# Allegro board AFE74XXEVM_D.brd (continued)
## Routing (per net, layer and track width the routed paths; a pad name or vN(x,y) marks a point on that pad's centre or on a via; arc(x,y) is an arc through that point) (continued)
FMC_SCL: length 50.4
  TOP w0.127: U31.6 189.03,22.71 190.07,23.75 190.07,27.48 J37.2 190.04,27.58 188.14,29.49 188.14,37.85 198.73,48.44 213.03,48.44 213.55,48.96 213.55,50.61 v2(212.73,51.43)
FMC_SDA: length 45.5
  TOP w0.127: U31.5 187.25,23.98 186.74,24.49 186.74,26.75 J37.1 187.5,38.05 199.03,49.58 212.14,49.58 v2(212.73,50.16)
FMC_SPIACLK: length 94.6
  L4_SIG w0.127: v2(211.46,75.56) 211.33,75.56 210.59,74.83 203.71,74.83 200.43,78.11 171.52,78.11 171.43,78.19 148.09,78.19 144.73,81.56 144.15,81.56 142.29,83.41 130.28,83.41 127.53,86.16 127.53,90.09 126.44,91.19 J13.6
FMC_SPIASDIO: length 91.2
  L4_SIG w0.127: v2(211.46,74.3) 212.28,75.12 212.28,76.8 211.8,77.28 203.65,77.28 203.65,77.28 203.47,77.28 201.59,79.16 149.64,79.16 149.59,79.11 149.12,79.11 148.76,79.48 148.76,79.92 143.69,84.99 136.27,84.99 135.15,86.11 135.15,86.69 134.19,87.66 133.6,87.66 132.79,88.47 132.79,89.05 131.52,90.32 J13.12
FMC_SPIASDO: length 116.9
  L4_SIG w0.127: J13.9 128.98,91.19 130.05,90.12 130.05,86.26 132.08,84.23 143.61,84.23 147.94,79.9 147.94,79.57 148.89,78.61 201.02,78.61 203.62,76.01 211.64,76.01 211.9,75.75 211.9,75.38 211.01,74.49 211.01,74.11 211.51,73.61 211.94,73.61 212.28,73.95 212.28,74.48 212.71,74.9 v2(213.23,74.9)
  L6_SIG w0.102: v2(211.46,56.52) 211.79,56.52 212.34,57.07 212.34,57.56 212.29,57.61 212.29,73.33 212.65,73.69 213.03,73.69 213.33,73.99 213.33,74.8 v2(213.23,74.9)
FMC_SPIASEN: length 118
  L4_SIG w0.127: v2(213.31,72.36) 209.85,72.36 209.45,72.77 209.45,73.3 209.07,73.69 203.84,73.69 203.67,73.85 203.65,73.85 203.39,74.11 203.39,74.13 200.66,76.86 171.17,76.86 170.38,77.65 147.93,77.65 144.58,81 143.18,81 141.38,82.8 128.17,82.8 124.97,86 124.97,90.3 123.93,91.34 J13.3
  L6_SIG w0.102: v2(213.31,72.36) 213.31,57.1 v2(211.46,55.24)
FMC_SPIBCLK: length 84.3
  L4_SIG w0.127: v2(208.36,80.01) 208.36,80.56 207.46,81.46 148.67,81.46 144.53,85.6 144.53,86.69 143.21,88.01 143.21,88.62 141.94,89.89 138,89.89 136.6,91.29 J13.18
  L8_PWR_SIG w0.127: v2(208.36,80.01) 209.75,78.61 209.75,78.3 209.74,78.29 209.74,75.38 209.75,75.37 209.75,74.73 v2(210.19,74.3)
FMC_SPIBSDIO: length 85.7
  L4_SIG w0.127: J13.24 142.98,91.34 145.64,88.67 145.64,85.93 148.64,82.93 203.46,82.93 203.65,82.74 204.02,82.74 204.16,82.88 204.78,82.88 204.92,82.74 205.29,82.74 205.43,82.88 206.05,82.88 206.19,82.74 206.56,82.74 206.7,82.88 207.32,82.88 207.46,82.74 207.83,82.74 207.97,82.88 209.17,82.88 v2(209.52,82.52)
  L8_PWR_SIG w0.127: v2(210.19,73.02) 210.57,73.02 211.23,73.69 211.68,73.69 211.77,73.77 211.77,73.79 212.03,74.05 212.05,74.05 212.14,74.14 212.14,78.94 210.87,80.21 210.87,80.59 210.37,81.09 209.94,81.09 209.52,81.51 v2(209.52,82.52)
FMC_SPIBSDO: length 88.5
  L4_SIG w0.127: J13.21 139.17,91.34 140.12,90.39 142.88,90.39 145.16,88.11 145.16,85.67 148.84,81.99 192.2,81.99 192.37,81.83 201.28,81.83 201.81,82.36 207.83,82.36 209.52,80.66 v2(209.52,79.96)
  L8_PWR_SIG w0.127: v2(209.52,79.96) 210.34,79.96 210.72,79.58 210.72,74.1 210.28,73.66 210.06,73.66 209.74,73.34 209.74,71.36 210.19,70.92 v2(210.19,70.48)
FMC_SPIBSEN: length 90.2
  L4_SIG w0.127: J13.15 135.23,90.17 136.73,90.17 137.92,88.98 137.92,88.52 138.84,87.6 141.88,87.6 148.4,81.09 148.62,81.09 148.81,80.9 202.44,80.9 203.2,80.14 v2(207.04,80.14)
  L8_PWR_SIG w0.127: v2(210.19,69.22) 210.19,69.57 209.36,70.4 209.36,77.02 208.86,77.52 208.69,77.52 207.04,79.17 v2(207.04,80.14)
FMC_TCK: length 106.2
  L4_SIG w0.102: v2(213.37,82.59) 213.37,83.22 212.78,83.82 203.48,83.82
  L4_SIG w0.127: J10.3 146.96,91.34 147.85,90.45 147.85,86.36 150.9,83.31 202.84,83.31 203.35,83.82 203.48,83.82
  L6_SIG w0.102: v2(211.46,52.7) 212.07,52.7 213.16,53.8 213.16,54.15 213.82,54.81 214.17,54.81 214.63,55.27 214.63,82.09 214.13,82.59 v2(213.37,82.59)
FMC_TDI: length 105.8
  L4_SIG w0.127: J10.6 150.65,89.99 152.35,89.99 153.03,89.31 153.03,88.37 153.72,87.68 154.79,87.68 155.83,86.64 155.83,85.62 157.63,83.82 202.11,83.82 203.3,85.01 v2(214.66,85.01)
  L8_PWR_SIG w0.102: v2(211.46,51.43) 211.4,51.43 210.72,52.12 210.72,57.89 214,61.16 214.17,61.16 214.71,61.7 214.71,84.96 v2(214.66,85.01)
FMC_TDO: length 107.1
  L4_SIG w0.102: 203.48,86.28 212.37,86.28 212.93,85.72 214.68,85.72 215.21,85.19 215.93,85.19
  L4_SIG w0.127: 203.48,86.28 201.5,84.3 158.8,84.3 157.96,85.14 157.96,87.05 157.38,87.63 156.74,87.63 155.35,89.03 155.35,89.59 154.84,90.09 152.98,90.09 151.84,91.24 J10.9 ; v1(216.2,85.19) 215.93,85.19
  L8_PWR_SIG w0.102: 215.93,61.64 212.9,58.62 212.83,58.62 212.09,57.89 212.09,50.85 211.46,50.22 v2(211.46,50.16)
  L8_PWR_SIG w0.127: v1(216.2,85.19) 216.2,61.92 215.93,61.64
FMC_TMS: length 107.4
  L4_SIG w0.127: v2(213.46,86.44) 212.27,87.63 203.53,87.63 200.69,84.79 159.23,84.79 158.39,85.62 158.39,89 157.25,90.14 155.52,90.14 154.38,91.29 J10.12
  L6_SIG w0.102: v2(213.46,86.44) 213.89,86.44 215.93,84.41 ; 215.93,55.29 212.07,51.43 212.07,48.24 v2(211.46,47.62)
  L6_SIG w0.127: 215.93,55.29 215.95,55.32 215.95,84.38 215.93,84.41
FMC_TRSTB: length 110.1
  L4_SIG w0.127: J10.15 156.92,91.19 158.93,89.18 158.93,85.85 159.51,85.27 200,85.27 203.66,88.93 213.44,88.93 v2(214.68,87.68)
  L6_SIG w0.102: v2(211.46,46.35) 212.07,46.35 213.16,47.45 213.16,47.8 213.82,48.46 214.17,48.46 214.43,48.72 214.43,49.07 215.09,49.73 215.44,49.73 215.7,49.99 215.7,50.34 215.57,50.47 215.93,50.83 ; v2(214.68,87.68) 215.24,87.68 215.93,86.99 215.93,86.44
  L6_SIG w0.127: 215.93,50.83 216.92,51.82 216.92,85.45 215.93,86.44
FMC_TXDSASW: length 94.7
  L6_SIG w0.127: J9.45 153.62,110.44 154.99,111.81 170.76,111.81 172.62,113.66 180.8,113.66 181.56,114.43 183.74,114.43 184.32,113.86 195.19,113.86 195.55,114.22 v1(197.1,114.22)
  L8_PWR_SIG w0.127: v2(208.92,71.75) 208.92,72.38 204.51,76.79 204.51,88.74 197.99,95.25 197.99,99.82 195.45,102.36 195.45,113.2 196.48,114.22 v1(197.1,114.22)
FMC_TXTDD1: length 108.2
  TOP w0.127: v1(149.86,108.64) 149.86,107.72 150.68,106.9 151.09,106.9 152.32,105.66 152.32,102.77 151.98,102.43 151.98,92.77 152.91,91.85 152.91,88.21 152.17,87.48 151.64,87.48 150.89,86.73 150.89,85.64 162.26,74.27 v1(162.84,74.27)
  L4_SIG w0.102: v1(208.92,69.22) 209.52,68.61 209.52,67.79 208.86,67.13 203.86,67.13 203.48,67.51
  L4_SIG w0.127: v1(162.84,74.27) 164.67,76.1 169.37,76.1 170.04,75.43 170.04,74.89 172.87,72.06 197.64,72.06 202.18,67.51 203.48,67.51
  BOTTOM w0.127: J9.27 139.04,110.39 140.46,108.97 149.53,108.97 v1(149.86,108.64)
FMC_TXTDD2: length 107.6
  L4_SIG w0.102: v1(208.92,67.94) 208.92,67.92 208.51,67.51 204.67,67.51 203.84,68.35 203.48,68.35
  L4_SIG w0.127: v1(141.33,79.63) 141.33,79.25 144.1,76.48 170.38,76.48 174.24,72.62 197.97,72.62 202.23,68.35 203.48,68.35
  L8_PWR_SIG w0.127: v1(141.33,79.63) 140.73,80.23 140.73,92.04 141.38,92.68 141.38,93.42 139.78,95.02 139.78,96.11 140.4,96.74 140.55,96.74 141.74,97.93 141.74,98.97 141,99.72 140.34,99.72 139.7,100.36 139.7,107.98 140.92,109.2 J9.30
FPGA_CLK1_N: length 98.4
  L6_SIG w0.127: v1(110.67,92.86) 111.1,92.86 111.19,92.95 121.12,92.95 121.75,92.32 169.4,92.32 171.82,89.9 171.82,88.23 173.56,86.49 175.23,86.49 178.1,83.62 203.68,83.62 203.84,83.46 v2(203.84,83.19)
FPGA_CLK1_P: length 98.4
  L6_SIG w0.127: v2(203.84,84.45) 203.84,84.2 203.68,84.05 178.28,84.05 175.41,86.92 173.74,86.92 172.25,88.41 172.25,90.08 169.58,92.75 121.93,92.75 121.3,93.38 111.19,93.38 111.1,93.47 v1(110.67,93.47)
FPGA_CLK1N: length 3.3
  BOTTOM w0.203: U3.52 107.33,93.11 107.42,93.19 108.7,93.19 108.83,93.07 109.11,93.07 109.35,92.84 R177.1 110.03,92.84 C241.1
FPGA_CLK1P: length 3.3
  BOTTOM w0.203: U3.51 107.31,93.61 107.39,93.52 108.84,93.52 108.96,93.4 109.25,93.4 109.35,93.5 R176.1 110.03,93.5 C240.1
FPGA_CLK2_N: length 98.4
  L6_SIG w0.102: v2(205.11,85.72) 205.11,85.95 204.9,86.16 203.67,86.16 203.66,86.14 203.48,86.14
  L6_SIG w0.127: 203.48,86.14 182.89,86.14 182.53,85.79 180.1,85.79 178.99,86.9 178.99,87.41 172.33,94.07 124.07,94.07 123.3,94.83 111.8,94.83 111.71,94.74 v1(111.28,94.74)
FPGA_CLK2_P: length 98.4
  L6_SIG w0.102: 203.48,86.58 203.49,86.58 203.5,86.56 204.93,86.56 205.11,86.74 v2(205.11,86.99)
  L6_SIG w0.127: 203.48,86.58 182.71,86.58 182.36,86.22 180.28,86.22 179.42,87.08 179.42,87.59 172.51,94.5 124.25,94.5 123.48,95.26 111.8,95.26 111.71,95.35 v1(111.28,95.35)
FPGA_CLK2N: length 4.2
  BOTTOM w0.203: U3.50 107.32,94.11 107.4,94.19 108.25,94.19 108.93,94.88 109.74,94.88 109.91,94.72 R182.1 110.64,94.72 C250.1
FPGA_CLK2P: length 4.2
  BOTTOM w0.203: C249.1 110.64,95.38 R183.1 109.91,95.38 109.74,95.21 108.8,95.21 108.11,94.52 107.43,94.52 107.35,94.61 U3.49
FSPICLKA: length 199.4
  L4_SIG w0.102: v1(56.75,57.5) 56.74,57.5 56.34,57.1 56.34,55.37 56.35,55.36
  L4_SIG w0.127: v1(162.43,41.91) 161.42,42.93 106.93,42.93 101.59,37.58 80.67,37.58 73.52,44.73 73.52,44.9 69.28,49.14 64.61,49.14 64.12,49.64 62.31,49.64 58.69,53.26 58.65,53.26 58.46,53.45 58.16,53.45 56.35,55.26 56.35,55.36
  L8_PWR_SIG w0.127: v1(162.43,41.91) 162.43,44.13 161.48,45.08 161.48,46.93 161.77,47.22 161.77,48.01 161.59,48.18 161.59,49.38 162,49.78 162,65.14 160.4,66.74 160.4,69.58 160.06,69.92 160.06,70.29 160.4,70.63 160.4,79.38 160.77,79.75 160.77,80.12 160.4,80.49 160.4,86.99 160.07,87.32 160.07,105.42 160.31,105.66 160.31,105.97 160.39,106.04 160.39,107.4 159.69,108.1 159.69,110.75 159.09,111.34 154.75,111.34 153.47,112.62 v1(151.97,112.62)
  BOTTOM w0.127: v1(151.97,112.62) R33.2
FSPICLKB: length 201.2
  L4_SIG w0.102: 54.74,55.36 54.74,57.02 54.35,57.41 v1(54.35,57.5)
  L4_SIG w0.127: 54.74,55.36 54.74,54.28 56.08,52.94 56.08,52.84 58.26,50.66 58.82,50.66 61.92,47.55 64.62,47.55 64.77,47.7 65.14,47.7 65.49,47.36 67.63,47.36 70.24,44.74 70.28,44.74 79.27,35.75 81.19,35.75 81.23,35.79 81.6,35.79 81.64,35.75 83.92,35.75 83.92,35.75 86.83,35.75 86.83,35.75 102.19,35.75 105.69,39.24 152.48,39.24 152.84,39.6 161.77,39.6 163.7,41.53 v1(163.7,41.91)
  L8_PWR_SIG w0.127: v1(163.7,41.91) 164.03,42.24 164.03,45.85 164.22,46.04 164.22,47.23 163.54,47.92 163.54,49.36 163.8,49.63 163.8,60.79 163.82,60.8 163.82,61.17 163.8,61.18 163.8,65.58 162.55,66.84 162.55,69.62 162.88,69.95 162.88,73.68 163.28,74.09 163.28,75.32 162.7,75.91 162.7,81.93 162.37,82.26 162.37,82.63 162.89,83.15 162.89,94.49 162.7,94.68 162.7,110.35 160.83,112.22 157.4,112.22 157.02,112.6 v1(157.02,112.65)
  BOTTOM w0.127: v1(157.02,112.65) R35.2
FSPICLKC: length 146.6
  L6_SIG w0.127: v1(68.49,113.75) 71.91,113.75 72.38,114.21 74.66,114.21 75.14,113.73 97.56,113.73 98.42,114.59 101.41,114.59 102.31,113.69 112.47,113.69 113,113.16 128.96,113.16 129.24,112.88 149.68,112.88 150.94,114.13 160.87,114.13 v1(162.33,112.67)
  BOTTOM w0.102: 57.15,71.5 57.15,69.88 56.77,69.5 v1(56.75,69.5)
  BOTTOM w0.127: v1(68.49,113.75) 67.95,113.21 67.95,101.59 63.47,97.11 63.47,83.33 62.79,82.64 62.79,80.49 58.38,76.08 58.2,76.08 57.15,75.03 57.15,71.5 ; v1(162.33,112.67) R36.2
FSPICLKD: length 156.7
  L6_SIG w0.127: v1(165.48,116.33) 165.46,116.31 163.8,116.31 163.27,115.77 162.51,115.77 162.18,116.1 150.57,116.1 148.06,113.59 130,113.59 129.75,113.84 113.54,113.84 112.14,115.24 98.45,115.24 97.95,114.74 83.64,114.74 83.63,114.74 70.89,114.74 70.82,114.67 67.46,114.67 67.44,114.65 v1(67.35,114.74)
  BOTTOM w0.102: v1(54.35,69.5) 53.98,69.87 53.98,71.5
  BOTTOM w0.127: R46.1 R39.2 165.48,113.44 v1(165.48,116.33) ; v1(67.35,114.74) 66.98,114.37 66.98,109.24 66.29,108.56 66.29,104.9 65.46,104.07 65.46,101.3 63.91,99.75 63.91,99.53 62.94,98.55 62.49,98.55 62.1,98.16 62.1,95.27 57.23,90.4 57.23,84.86 54.33,81.97 54.33,77.66 53.88,77.21 53.88,73.33 54.02,73.19 54.02,71.55 53.98,71.5
FSPIDA: length 195.1
  L4_SIG w0.102: 57.15,55.36 57.15,57.15 57.5,57.5 v1(57.55,57.5)
  L4_SIG w0.127: v1(162.94,44.45) 161.93,43.43 106.3,43.43 100.99,38.13 81,38.13 69.49,49.63 65.24,49.63 64.66,50.21 62.65,50.21 61.55,51.3 61.55,51.3 61.29,51.56 61.29,51.57 59.1,53.75 58.51,53.75 57.15,55.12 57.15,55.36
  L8_PWR_SIG w0.127: v1(154.46,112.65) 154.46,112.62 155.27,111.81 159.51,111.81 160.12,111.2 160.12,110.11 160.88,109.35 161.42,109.35 162.32,108.45 162.32,96.13 162.19,96 162.19,94.5 162.33,94.36 162.33,90.82 161.73,90.23 161.73,89.86 162.33,89.26 162.33,85.88 161.82,85.37 161.82,80.13 161.81,80.12 161.81,79.75 161.86,79.7 161.86,66.1 162.62,65.34 162.62,59.07 162.65,59.05 162.65,56.03 163.23,55.44 163.23,54.73 162.73,54.22 162.73,48.17 162.52,47.97 162.52,47.21 162.94,46.79 v1(162.94,44.45)
  BOTTOM w0.127: v1(154.46,112.65) R32.2
FSPIDB: length 201
  L4_SIG w0.102: 55.59,55.36 55.53,55.42 55.53,57.24 55.28,57.5 v1(55.15,57.5)
  L4_SIG w0.127: 55.59,55.36 56.64,54.31 56.64,53.88 58.49,52.03 58.63,52.03 60.16,50.5 60.16,50.21 62.34,48.02 62.75,48.02 63.11,48.38 68.58,48.38 80.38,36.58 82.09,36.58 82.54,36.13 83.48,36.13 83.92,36.58 101.98,36.58 105.71,40.31 161.59,40.31 162.94,41.66 162.94,41.91 163.45,42.42 164.08,42.42 164.59,41.91 v1(164.85,41.91)
  L8_PWR_SIG w0.127: v1(159.64,112.67) 161.34,112.67 162.46,111.56 164.06,111.56 165.1,110.52 165.1,99.64 164.74,99.29 164.74,91.85 165.07,91.52 165.07,91.03 164.53,90.48 164.53,89.52 164.97,89.08 164.97,85.65 164.71,85.38 164.71,71.27 165.74,70.24 165.74,49.65 165.44,49.36 165.44,47.39 165.18,47.12 165.18,45.44 165.49,45.12 165.49,43.14 164.86,42.5 164.86,41.92 v1(164.85,41.91)
  BOTTOM w0.127: v1(159.64,112.67) R34.2
FSPIDC: length 148.1
  L6_SIG w0.127: v1(164.62,112.67) 164.16,112.22 161.67,112.22 160.77,113.12 151.22,113.12 150.5,112.39 129.26,112.39 128.83,111.96 127.15,111.96 127,112.12 109.42,112.12 108.81,111.5 102.75,111.5 100.72,113.53 98.65,113.53 97.73,112.61 96.55,112.61 96.12,113.04 75.31,113.04 75.21,112.94 69.36,112.94 v1(69.27,113.04)
  BOTTOM w0.102: 57.92,71.5 57.92,70.07 57.55,69.69 v1(57.55,69.5)
  BOTTOM w0.127: 57.92,71.5 57.92,72.03 57.8,72.15 57.77,72.15 57.51,72.41 57.51,72.78 57.83,73.11 57.83,74.46 62.94,79.56 63.4,79.56 64.1,80.26 64.1,86.55 64.61,87.05 64.61,97.54 68.49,101.41 68.49,112.26 v1(69.27,113.04) ; v1(164.62,112.67) R37.2
FSPIDD: length 142.3
  L4_SIG w0.102: v1(55.15,69.5) 55.15,69.72 54.77,70.1 54.77,71.5
  L4_SIG w0.127: v1(168.78,112.67) 168.78,112.69 167.34,114.13 159.45,114.13 159.43,114.11 151.81,114.11 151.64,113.94 139.34,113.94 136.91,111.51 136.91,110.11 135.76,108.97 132.97,108.97 131.71,107.71 131.71,104.53 131.01,103.84 125.7,103.84 121.91,100.04 116.88,100.04 116.46,100.46 108.08,100.46 107.57,99.95 105.41,99.95 104.52,99.06 101.85,99.06 101.46,99.45 94.12,99.45 88.68,94.02 88.68,93.82 87.7,92.84 83.16,92.84 81.89,91.56 81.89,90.94 79.29,88.34 79.11,88.34 75.77,85 65.03,85 64.63,84.59 62.77,84.59 59.77,81.6 59.61,81.6 59.35,81.34 59.35,80.96 56.17,77.78 56.17,75.18 54.77,73.78 54.77,71.5
  BOTTOM w0.127: R47.1 v1(168.78,112.67)
FTDI_DSASW: length 57.6
  TOP w0.127: JP7.1 151.43,123.32 149.96,121.84 149.96,113.21 152.04,111.12 152.04,109.63 152.81,108.86 153.95,108.86 154.57,108.24 154.57,106.26 J9.43 ; U10.4 v1(180.87,97.69)
  BOTTOM w0.127: v1(180.87,97.69) 180.73,97.55 178.84,97.55 176.62,99.76 173.69,99.76 173.38,100.08 173.38,102.63 171.67,104.34 157.12,104.34 J9.46 J9.43 ; JP7.1 151.43,123.39 R24.1 C45.2
FTDI_FBBANDSEL: length 59.4
  TOP w0.127: JP8.1 155.88,123.44 150.52,118.08 150.52,113.18 152.53,111.18 152.53,110.13 153.22,109.44 154.06,109.44 155.12,108.38 155.12,107.49 156.35,106.26 156.96,106.26 157.91,105.31 J9.49 ; U10.5 v1(180.21,97.99)
  BOTTOM w0.127: JP8.1 158.57,123.39 R25.1 C46.2 ; J9.49 J9.52 162.33,106.4 174.4,106.4 176.05,104.75 176.05,104 176.08,103.97 176.08,103.48 176.17,103.39 176.17,100.46 176.3,100.33 178.45,100.33 180.21,98.56 v1(180.21,97.99)
FTDI_FSPICLKA: length 32.2
  TOP w0.127: J12.2 154.99,121.08 181.41,121.08 181.9,120.59 U6.1
FTDI_FSPICLKB: length 25.9
  TOP w0.127: J12.6 159.16,120.17 179.35,120.17 180.48,119.04 U6.4
FTDI_FSPICLKC: length 20.7
  TOP w0.127: U6.6 179.96,118.04 178.56,119.43 163.5,119.43 J12.10
FTDI_FSPICLKD: length 15.3
  TOP w0.127: U6.8 179.56,117.04 178.02,118.58 167.73,118.58 J12.14
FTDI_FSPIDA: length 28.7
  TOP w0.127: J12.4 157.1,120.65 179.35,120.65 180.46,119.54 U6.3
FTDI_FSPIDB: length 23.3
  TOP w0.127: U6.5 180.42,118.54 179.15,119.81 161.34,119.81 J12.8
FTDI_FSPIDC: length 18
  TOP w0.127: U6.7 179.69,117.54 178.23,119 165.61,119 J12.12
FTDI_FSPIDD: length 12.2
  TOP w0.127: J12.16 178.21,117.63 179.3,116.54 U6.9
FTDI_RXDSAFAST: length 92.6
  TOP w0.127: U10.2 v1(182.18,96.86) ; JP2.1 116.92,121.72 116.92,106.5 118.06,105.36 J9.1
  BOTTOM w0.127: C42.2 R27.1 115.27,123.37 JP2.1 ; J9.1 J9.4 J9.7 J9.10 127.38,103.61 140.49,103.61 142.28,101.82 151.45,101.82 151.87,101.4 152.68,101.4 153.1,101.82 154.22,101.82 154.64,101.4 155.22,101.4 155.64,101.82 156.5,101.82 156.92,101.4 157.76,101.4 158.18,101.82 169.33,101.82 172.39,98.76 176.49,98.76 178.6,96.65 181.97,96.65 v1(182.18,96.86)
FTDI_RXFBNCO: length 82.1
  TOP w0.127: J9.13 128.22,105.33 129.17,106.29 129.17,111.31 128.68,111.8 128.68,112.64 122.56,118.76 JP3.1 ; U10.3 v1(181.53,97.33)
  BOTTOM w0.127: v1(181.53,97.33) 181.36,97.16 178.66,97.16 176.48,99.34 172.75,99.34 169.65,102.44 142.67,102.44 140.97,104.14 137.01,104.14 J9.22 J9.19 J9.16 J9.13 ; C47.2 R28.1 122.5,123.37 JP3.1
FTDI_RXFBSW: length 51
  TOP w0.127: U9.9 172.62,100.74 v1(172.42,100.53) ; JP6.1 145.69,121.89 145.69,113.33 147.55,111.48 147.55,106.3 J9.37
  BOTTOM w0.127: J9.37 J9.40 152.04,104.34 156.39,104.34 156.87,103.86 171.45,103.86 172.95,102.36 172.95,101.07 v1(172.42,100.53) ; C44.2 142.57,123.29 R23.1 144.22,123.27 JP6.1
FTDI_RXTDD_MODE: length 55.9
  TOP w0.127: U9.8 v1(172.47,101.24) ; J9.31 143.46,105.89 142.38,106.97 142.38,110.73 138.07,115.04 138.07,119.99 137.16,120.9 JP5.1
  BOTTOM w0.127: JP5.1 137.13,123.34 R22.1 C43.2 ; v1(172.47,101.24) 172.47,102.16 171.31,103.31 156.4,103.31 155.97,103.75 151.52,103.75 151.09,103.31 147.99,103.31 J9.34 J9.31
FTDI_SPIACLK: length 81
  TOP w0.127: U7.3 v1(172.55,110.72) ; J13.4 127.97,87.78 127.97,92.15 129.67,93.85 129.67,111.4 v1(129.46,111.61)
  L4_SIG w0.127: v1(172.55,110.72) 172.55,116.5 170.31,118.74 135.25,118.74 129.54,113.03 129.54,111.68 v1(129.46,111.61)
FTDI_SPIASDIO: length 74.1
  TOP w0.127: v1(134.77,111.38) 134.77,101.27 134.76,101.26 134.76,95.39 134.77,95.38 134.77,93.55 133.05,91.82 133.05,87.78 J13.10 ; U7.5 v1(172.5,109.72)
  L4_SIG w0.127: v1(134.77,111.38) 134.77,114.58 136.23,116.04 162.29,116.04 162.42,115.91 163.71,115.91 163.84,116.04 165.14,116.04 165.3,115.89 166.23,115.89 166.38,116.04 169.71,116.04 171.07,114.68 171.07,110.41 171.76,109.72 v1(172.5,109.72)
FTDI_SPIASDO: length 76.6
  TOP w0.127: J13.7 130.07,87.35 130.07,93.68 131.72,95.33 131.72,111.18 v1(132.11,111.56) ; U7.4 v1(171.92,110.22)
  L4_SIG w0.127: v1(171.92,110.22) 171.92,114.72 170.05,116.59 165.86,116.59 165.67,116.78 165.3,116.78 165.11,116.59 163.29,116.59 163.07,116.8 162.71,116.8 162.49,116.59 135.13,116.59 132.11,113.56 v1(132.11,111.56)
FTDI_SPIASEN: length 84.1
  TOP w0.127: U7.1 174.15,111.8 v1(173.71,112.24) ; J13.1 125.2,87.55 126.75,87.55 127.51,88.32 127.51,91.92 127.14,92.29 127.14,112.08 v1(127.56,112.5)
  L4_SIG w0.127: v1(173.71,112.24) 173.48,112.47 173.48,116.46 170.56,119.38 135.03,119.38 128.78,113.13 128.19,113.13 v1(127.56,112.5)
FTDI_SPIBCLK: length 62
  TOP w0.127: U7.7 v1(172.53,108.72) ; v1(139.65,108.69) 139.62,93.9 138,92.28 138,87.66 J13.16
  L4_SIG w0.127: v1(172.53,108.72) 171.39,108.72 170.98,109.13 168.69,109.13 167.69,110.13 167.69,110.95 166.46,112.18 144.99,112.18 144.96,112.2 144.6,112.2 144.57,112.18 140.86,112.18 139.65,110.97 v1(139.65,108.69)
FTDI_SPIBSDIO: length 53.2
  TOP w0.127: J13.22 144.41,88.99 144.41,101.89 144.98,102.46 144.98,105.74 v1(144.68,106.05) ; U7.9 v1(172.54,107.72)
  L4_SIG w0.127: v1(144.68,106.05) 144.68,104.96 145.53,104.11 149,104.11 149.85,104.97 149.85,105.52 150.62,106.29 154.83,106.29 154.91,106.36 155.28,106.36 155.35,106.29 160.05,106.29 160.06,106.27 170.74,106.27 172.19,107.72 v1(172.54,107.72)
FTDI_SPIBSDO: length 53.6
  TOP w0.127: v1(141.96,106.53) 142.09,106.4 142.09,104.42 141.76,104.09 141.76,95.17 140.18,93.6 140.18,87.3 J13.19 ; U7.8 v1(171.96,108.22)
  L4_SIG w0.127: v1(171.96,108.22) 170.39,106.65 155.42,106.65 155.4,106.67 154.78,106.67 154.77,106.65 142.09,106.65 v1(141.96,106.53)
FTDI_SPIBSEN: length 64.7
  TOP w0.127: U7.6 v1(171.94,109.22) ; J13.13 135.59,87.78 135.59,91.72 137.26,93.4 137.26,108.84 v1(137.52,109.09)
  L4_SIG w0.127: v1(137.52,109.09) 137.43,109.18 137.43,111.14 139.45,113.16 167.67,113.16 171.42,109.4 171.76,109.4 v1(171.94,109.22)
FTDI_TCK: length 45.3
  TOP w0.127: J10.1 147.88,87.38 147.88,92.13 147.4,92.61 147.4,101.8 v1(149.68,104.09) ; U9.1 174.03,104.84 v1(173.56,105.31)
  L4_SIG w0.127: v1(173.56,105.31) 172.82,106.05 170.94,106.05 169.1,104.2 149.8,104.2 v1(149.68,104.09)
FTDI_TDI: length 43.4
  TOP w0.127: v1(150.9,103.76) 149.45,102.31 149.45,93.19 148.34,92.08 148.34,87.22 J10.4 ; v1(171.31,105.6) 171.49,105.42 171.49,104.25 172,103.74 U9.3
  L4_SIG w0.127: v1(171.31,105.6) 171.13,105.6 169.29,103.76 v1(150.9,103.76)
FTDI_TDO: length 40
  TOP w0.127: J10.7 153.42,87.83 153.42,92.3 152.37,93.34 v1(152.4,101.96) ; v1(171.07,104.85) 171.07,103.89 171.7,103.25 172.33,103.25 172.34,103.24 U9.4
  L4_SIG w0.127: v1(171.07,104.85) 169.16,102.95 156.24,102.95 155.98,102.69 153.14,102.69 v1(152.4,101.96)
FTDI_TMS: length 35.3
  TOP w0.127: v1(155.07,101.96) 155.07,92.58 155.6,92.05 155.6,88.67 155.35,88.42 155.35,87.22 J10.10 ; v1(170.89,101.93) 171.7,102.74 U9.5
  L4_SIG w0.127: v1(155.07,101.96) 156.69,101.96 157.28,102.54 170.28,102.54 v1(170.89,101.93)
FTDI_TRSTB: length 33
  TOP w0.127: v1(171.42,101.52) 171.4,101.8 171.84,102.24 U9.6 ; J10.13 158.06,87.4 158.06,92.96 157.45,93.57 v1(157.4,101.85)
  L4_SIG w0.127: v1(157.4,101.85) 157.61,102.06 169.93,102.06 170.66,101.32 171.22,101.32 v1(171.42,101.52)
FTDI_TXTDD_MODE: length 62
  TOP w0.127: JP4.1 131.83,121.41 131.83,115.98 137.08,110.72 137.08,110.13 137.78,109.44 138.34,109.44 139.23,108.55 139.23,108.51 139.33,108.41 139.33,106.24 138.4,105.31 J9.25 ; v1(172.01,101.73) 172.02,101.74 U9.7
  BOTTOM w0.127: C48.2 127.99,123.22 R29.1 129.79,123.19 JP4.1 ; J9.25 J9.28 143.36,102.87 155.12,102.87 155.14,102.86 155.51,102.86 155.52,102.87 170.87,102.87 v1(172.01,101.73)
GBTCLK1_M2C_N: length 142.3
  BOTTOM w0.102: 215.86,70.14 215.74,70.02 212.39,70.02 212.01,69.64 212.01,63.79 212.4,63.4 213.89,63.4 214,63.3 v2(214,62.86)
  BOTTOM w0.203: 215.86,70.14 216.03,70.3 216.03,70.61 216.23,70.82 216.54,70.82 216.76,71.04 216.76,87.85 215.76,88.85 202.65,88.85 197.11,83.31 121.69,83.31 113.88,91.12 111.88,91.12 111.74,90.98 v1(111.28,90.98)
GBTCLK1_M2C_P: length 142.3
  BOTTOM w0.102: v2(214,64.14) 214,63.88 213.74,63.63 212.5,63.63 212.24,63.88 212.24,69.55 212.48,69.79 215.93,69.79
  BOTTOM w0.203: v1(111.28,91.59) 111.74,91.59 111.88,91.45 114.02,91.45 121.83,83.64 196.98,83.64 202.51,89.18 215.9,89.18 217.09,87.99 217.09,70.9 215.98,69.79 215.93,69.79
GTX_CLKM: length 108.6
  BOTTOM w0.102: 203.48,83.65 203.5,83.65 203.56,83.71 211.35,83.71 211.46,83.6 J32.D5
  BOTTOM w0.203: C224.2 106.2,82.14 106.2,81.53 107.59,80.14 122.56,80.14 123.25,80.82 198.49,80.82 201.32,83.65 203.48,83.65
GTX_CLKP: length 108.6
  BOTTOM w0.102: J32.D4 211.46,84.04 211.35,83.93 203.53,83.93 203.48,83.99
  BOTTOM w0.203: 203.48,83.99 201.18,83.99 198.35,81.15 123.11,81.15 122.43,80.47 107.73,80.47 107.47,80.73 107.47,80.98 107.55,81.07 107.55,81.32 107.37,81.5 107.12,81.5 107.04,81.42 106.78,81.42 106.53,81.67 106.53,82.12 C221.2
GTXCLKM: length 3.7
  BOTTOM w0.203: C224.1 106.05,82.91 R154.1 106.21,83.68 106.21,84.41 105.67,84.95 105.67,85.82 105.59,85.9 U3.2
GTXCLKP: length 3.7
  BOTTOM w0.203: C221.1 106.71,82.91 R155.1 106.54,83.68 106.54,84.55 106,85.08 106,85.79 106.09,85.87 U3.1
IOUTA: length 21.7
  TOP w0.381: R136.1 R139.1 25.04,42.11 arc(24.37,41.43) 23.88,40.61 17.97,27.33 arc(17.53,26.65) 16.91,26.14 J22.1
IOUTB: length 24.1
  TOP w0.381: J23.1 7.23,42.58 arc(8.16,43.26) 8.94,44.1 19.18,57.51 19.39,57.72 arc(20,58.13) 20.72,58.27 R143.1 R140.1
IOUTC: length 20.5
  TOP w0.381: J24.1 17.43,101.15 arc(18.26,100.51) 18.9,99.67 25.18,88.57 arc(25.68,87.78) 26.27,87.06 26.37,86.95 R147.1 R144.1
IOUTD: length 22.3
  TOP w0.381: R148.1 R151.1 20.74,70.98 20.64,71 arc(19.67,71.32) 18.87,71.95 10.01,81.81 arc(8.62,83.15) 7.04,84.26 J25.1
LMK LOCKED:
  vias: v1(114.02,82.58)
LMK_CLKIN: length 15.7
  BOTTOM w0.381: J26.1 95.89,116.86 arc(96.07,115.93) 96.6,115.14 97.22,114.51 arc(97.77,113.7) 97.96,112.74 R164.1 R161.1
LMK_CS: length 84.3
  L4_SIG w0.127: J36.11 167.64,90.14 167.64,92.53 165.68,94.49 113.28,94.49 109.65,90.86 106.45,90.86 105.98,90.39 96.79,90.39 95.35,88.95 95.35,87.22 95.71,86.87 96.55,86.87 v1(96.8,87.12)
  BOTTOM w0.127: U3.18 97.28,87.6 v1(96.8,87.12)
LMK_SCK: length 72.3
  L4_SIG w0.127: v1(96.77,87.76) 97.98,87.76 98.56,88.35 106.44,88.35 107.35,89.27 109.92,89.27 110.29,88.9 117.35,88.9 117.53,89.08 119.02,89.08 123.62,93.68 159.61,93.68 160.3,92.99 160.3,90.73 161.37,89.66 J36.2
  BOTTOM w0.127: v1(96.77,87.76) 97.11,88.1 U3.19
LMK_SDIO: length 75.1
  L4_SIG w0.127: J36.5 162.86,89.84 162.86,92.81 161.57,94.11 123.6,94.11 119.49,90 114.16,90 114.02,89.87 106.81,89.87 106.24,89.29 99.17,89.29 98.95,89.51 97.23,89.51 96.72,89 v1(96.72,88.43)
  BOTTOM w0.127: U3.20 96.9,88.6 v1(96.72,88.43)
LMK_SDO: length 70.7
  L4_SIG w0.127: J36.8 165.49,87.85 160.76,87.85 159.74,88.86 159.74,90.47 157.48,92.74 123.32,92.74 122.22,91.64 122.22,87.91 121.62,87.3 112.24,87.3 111.25,86.31 104.5,86.31 104.22,86.59 v3(104.09,86.59)
NB7_RESET: length 145.1
  L4_SIG w0.127: v1(201.68,64.54) 199.42,66.8 198.5,66.8 196.39,68.91 166.9,68.91 163.87,71.95 126.59,71.95 126.33,71.69 126.33,71.67 125.83,71.17 v1(125.83,70.84) ; v1(91.9,102.11) 93.08,102.11 93.91,102.93 105.3,102.93 106.17,103.81 120.95,103.81 121.92,102.84 v1(121.97,102.84)
  L8_PWR_SIG w0.127: v1(121.97,102.84) 124.49,100.33 124.49,93.34 125.35,92.48 125.35,86 125.78,85.57 v1(125.83,70.84)
  BOTTOM w0.203: U2.15 v1(91.9,102.11)
Net_11:
  vias: v2(214,52.7)
Net_12:
  vias: v2(214,53.97)
Net_13:
  vias: v2(214,57.78)
Net_14:
  vias: v2(214,59.05)
OSCI: length 5.7
  TOP w0.203: U5.2 188.22,104.5 v1(187.73,104.01)
  BOTTOM w0.203: v1(187.73,104.01) 187.07,104.67 186.79,104.67 185.94,105.52 Y2.1
OSCINN: length 3.2
  BOTTOM w0.203: U3.44 104.09,96.26 104.01,96.33 104.01,96.91 103.68,97.24 103.68,97.59 C255.2 103.84,98.35 C252.2
OSCINP: length 3.2
  BOTTOM w0.203: C245.2 103.17,98.35 C247.2 103.35,97.56 103.35,97.1 103.68,96.77 103.68,96.35 103.59,96.26 U3.43
OSCO: length 5.7
  TOP w0.203: v1(189.15,107.34) 189.2,107.29 189.2,105.2 189.41,105 U5.3
  BOTTOM w0.203: Y2.3 188.41,107.06 188.67,107.06 188.95,107.34 v1(189.15,107.34)
OSCP: length 1.9
  BOTTOM w0.381: C244.2 103.2,100.25 R175.2 R180.1 103.2,99.59 C245.1
PG_2P2V: length 42.2
  TOP w0.127: U18.5 v1(168.21,12.66)
  L8_PWR_SIG w0.127: v1(151.74,29.44) 151.74,19.94 157.99,13.69 v1(157.99,8.43) 157.99,8.33 159.97,6.35 166.42,6.35 168.21,8.14 v1(168.21,12.66)
  BOTTOM w0.127: R273.2 v1(151.74,29.44)
PG_C2M:
  vias: v2(211.46,88.27)
PG_DVDD1P0V: length 58.8
  TOP w0.127: R326.1 v1(142.54,26.82) ; U16.22 v1(156.42,7.58)
  TOP w0.305: U27.4 144.59,27.11 144.3,26.82 R326.1
  L8_PWR_SIG w0.127: v1(142.54,26.82) 142.54,25.88 144.37,24.05 146.13,24.05 156.42,13.76 v1(156.42,7.58)
  BOTTOM w0.127: v1(142.54,26.82) 142.49,26.87 141.27,26.87 130.86,16.46 125.86,16.46 121.77,12.37 R251.2
PG_M2C: length 4.6
  TOP w0.127: R286.2 211.61,90.96 209.3,88.65
  TOP w0.152: 209.3,88.65 v2(208.92,88.27)
PG_RX1P2V: length 63.3
  TOP w0.127: R279.2 135.76,22.15 132.99,19.38 126.8,19.38 126.34,19.84 121.51,19.84 121.23,19.56 117.4,19.56 115.65,21.31 115.65,22 v1(114.76,22.89)
  TOP w0.305: v1(114.76,22.89) 114.88,23.01 115.52,23.01 115.63,23.12 U23.4
  BOTTOM w0.127: v1(114.76,22.89) 114.73,22.89 114.05,23.57 101.24,23.57 97.38,19.71 89.79,19.71 89.13,19.05 89.13,17.58 88.39,16.84 86.08,16.84 85.04,17.88 R257.2
PG_RX1P85V: length 42.4
  TOP w0.127: Q25.2 v1(92.68,18.06)
  TOP w0.305: v1(123.8,6.68) 124.38,6.68 124.72,7.02 U25.4
  L4_SIG w0.127: v1(123.8,6.68) 108.86,6.68 107.26,8.28 95.45,8.28 92.68,11.05 v1(92.68,18.06)
PG_TX1P0V: length 32.5
  TOP w0.305: v1(112.42,9.78) 112.9,9.78 113.22,10.09 U20.4
  L3_PWR w0.127: v1(122.81,25.25) 126.49,25.25 127.18,24.56 127.18,21.82 126.34,20.98 126.34,17.01 121.92,12.6 115.06,12.6 112.42,9.96 v1(112.42,9.78)
  BOTTOM w0.127: R261.2 v1(122.81,25.25)
PG_TX1P8V: length 71
  TOP w0.127: v1(126.52,22.5) 127.04,23.02 U29.4
  TOP w0.305: U22.4 82.74,24.83 82.42,25.15 v1(82.42,25.65)
  L4_SIG w0.127: v1(132,9.32) 132,9.55 132.59,10.13 132.59,12.95 126.52,19.02 v1(126.52,22.5)
  BOTTOM w0.127: v1(82.42,25.65) 82.47,25.65 84.12,27.3 95.96,27.3 99.03,24.23 114.3,24.23 115.54,22.99 115.54,21.01 117.17,19.38 121.31,19.38 124.41,22.48 126.49,22.48 v1(126.52,22.5) ; R267.2 v1(132,9.32)
PLL2 LOCKED:
  vias: v1(114.05,84.48)
PLL_CLKLD: length 1.5
  BOTTOM w0.127: Q2.1 121.56,98.2 J8.3
PLL_REFLD: length 1.6
  BOTTOM w0.127: Q1.1 119.15,98.07 J8.1
PLLCLKLD: length 104.6
  L4_SIG w0.102: v1(52.75,67.9) 52.33,68.32 52.31,68.3 51.01,68.3 50.77,68.54 50.77,71.33 50.94,71.5
  L4_SIG w0.127: 50.94,71.5 51.35,71.91 51.35,72.28 51.19,72.44 51.19,81.17 51.41,81.39 51.41,81.75 51.19,81.97 51.19,94.91 54.37,98.09 54.37,98.55 56.42,100.6 58.09,100.6 59.14,99.55 60.96,99.55 61.27,99.86 62.68,99.86 62.99,100.17 62.99,100.19 63.25,100.45 63.62,100.45 63.72,100.35 69.57,100.35 69.88,100.04 80.64,100.04 81.68,101.09 91.06,101.09 91.46,100.69 94.27,100.69 94.77,101.19 99.09,101.19 100.13,102.23 120.07,102.23 J8.4
PLLREFLD: length 169.8
  TOP w0.127: v1(115.37,110.93) 116.36,109.94 116.36,104.39 118.77,101.98 J8.2
  L6_SIG w0.102: v1(52.75,59.1) 52.7,59.1 52.32,58.72 49.15,58.72
  L6_SIG w0.127: 49.15,58.72 49.12,58.72 49.11,58.71 48.83,58.71 48.77,58.78 44.46,58.78 44.33,58.9 44.07,59.16 43.39,59.16 41.37,57.14 34.9,57.14 34.63,56.87 33,56.87 32.49,56.36 30.73,56.36 28.41,58.68 28,58.68 25.45,61.22 25.45,62.44 27.46,64.44 27.46,66.89 26.98,67.36 26.98,84.05 28.24,85.31 28.88,85.31 29.97,86.4 29.97,86.98 33.69,90.7 33.69,92.26 35.17,93.74 35.17,94.33 38.29,97.45 39.8,97.45 40.32,97.97 41.69,97.97 42.64,98.92 42.64,99.26 45.66,102.27 45.66,102.66 45.92,102.92 46.41,102.92 47.49,104 47.98,104 53.02,109.04 53.04,109.04 56.62,112.63 62.34,112.63 63.15,111.82 63.52,111.82 63.93,112.23 98.55,112.23 98.74,112.42 100.98,112.42 102.51,110.9 109.25,110.9 109.63,111.28 110,111.28 110.35,110.93 v1(115.37,110.93)
PRESENT:
  vias: v2(206.38,86.99)
RX1N: length 15.5
  L6_SIG w0.127: v1(63.95,55.9) 63.77,55.72 63.77,54.83 65.09,53.5 65.25,53.5 65.43,53.69 65.59,53.69 65.7,53.58 65.7,53.42 65.52,53.23 65.52,53.08 65.86,52.73 76.43,52.73 v1(76.53,52.83)
RX1P: length 15.5
  L6_SIG w0.127: v1(76.53,52.2) 76.43,52.3 65.68,52.3 63.33,54.65 63.33,55.72 v1(63.15,55.9)
RX2N: length 13.3
  L6_SIG w0.127: v1(76.53,55.75) 76.43,55.65 75.6,55.65 74.79,54.84 68.33,54.84 65.87,57.3 64.95,57.3 v1(64.75,57.5)
RX2P: length 13.3
  L6_SIG w0.127: v1(64.75,56.7) 64.92,56.87 65.69,56.87 68.16,54.41 74.97,54.41 75.78,55.22 76.43,55.22 v1(76.53,55.12)
RX3N: length 12.7
  L6_SIG w0.127: v1(76.53,58.8) 76.43,58.7 72.97,58.7 72.56,58.3 69.13,58.3 67.71,59.72 64.93,59.72 v1(64.75,59.9)
RX3P: length 12.7
  L6_SIG w0.127: v1(64.75,59.1) 64.93,59.28 67.53,59.28 68.95,57.86 72.74,57.86 73.14,58.27 76.43,58.27 v1(76.53,58.17)
RX4N: length 12.1
  L6_SIG w0.127: v1(76.53,61.85) 76.43,61.75 71.5,61.75 71.05,62.19 64.86,62.19 v1(64.75,62.3)
RX4P: length 12.1
  L6_SIG w0.127: v1(76.53,61.21) 76.43,61.32 71.32,61.32 70.88,61.76 65.01,61.76 v1(64.75,61.5)
RX5N: length 12.1
  L6_SIG w0.127: v1(64.75,64.7) 64.93,64.88 71.28,64.88 71.83,64.34 76.45,64.34 v1(76.53,64.26)
RX5P: length 12.1
  L6_SIG w0.127: v1(64.75,65.5) 64.93,65.32 71.46,65.32 72.01,64.77 76.4,64.77 v1(76.53,64.9)
RX6N: length 12
  L6_SIG w0.127: v1(76.53,67.31) 76.43,67.41 72.01,67.41 71.87,67.27 64.92,67.27 v1(64.75,67.1)
RX6P: length 12
  L6_SIG w0.127: v1(76.53,67.94) 76.43,67.84 71.83,67.84 71.69,67.71 64.94,67.71 v1(64.75,67.9)
RX7N: length 12.2
  L6_SIG w0.127: v1(76.53,70.36) 76.43,70.46 69.7,70.46 68.92,69.68 64.93,69.68 v1(64.75,69.5)
RX7P: length 12.2
  L6_SIG w0.127: v1(64.75,70.3) 64.93,70.12 68.74,70.12 69.52,70.89 76.43,70.89 v1(76.53,70.99)
RX8N: length 19.8
  L6_SIG w0.127: v1(76.53,73.41) 76.43,73.51 72.72,73.51 69.09,77.14 66.07,77.14 65.72,76.79 65.72,76.49 65.6,76.37 65.29,76.37 64.42,75.49 64.42,75.33 64.54,75.21 64.54,75.05 64.42,74.94 64.27,74.94 64.15,75.06 63.99,75.06 63.77,74.84 63.77,71.28 v1(63.95,71.1)
RX8P: length 19.8
  L6_SIG w0.127: v1(76.53,74.04) 76.43,73.94 72.9,73.94 69.27,77.57 65.89,77.57 63.33,75.02 63.33,71.28 v1(63.15,71.1)
RX_1.2V: length 17
  TOP w0.305: C81.1 116.84,34.26 v1(117.09,34.52) v1(117.86,34.52)
  L3_PWR w0.102: 58.65,60.96 58.53,61.08 58.19,61.08 58.08,60.97 57.82,60.97 57.71,61.08 57.39,61.08 57.25,60.93 57.23,60.93 ; 58.73,66.14 58.51,65.92 58.19,65.92 57.97,66.14 57.96,66.14 57.74,65.92 57.39,65.92 57.21,66.1 57.09,66.1 56.91,65.92 56.59,65.92 56.39,66.12 56.31,66.12
  BOTTOM w0.102: 61.93,59.72 62,59.72 62.19,59.53 62.51,59.53 62.76,59.78 62.78,59.77 62.78,59.74 62.99,59.53 64.11,59.53 64.34,59.76 64.34,59.82 64.38,59.78 64.38,59.74 64.59,59.53 64.91,59.53 65.15,59.77 ; 61.9,67.21 61.93,67.21 62.19,67.47 62.52,67.47 62.79,67.21 ; 65.13,67.26 65.12,67.26 64.91,67.47 64.53,67.47 64.34,67.28 64.34,67.16
  BOTTOM w0.127: 65.15,59.77 65.17,59.79 65.18,59.79
  BOTTOM w0.305: 66.93,65.1 66.9,65.07 v3(66.9,64.19) C84.1 C85.1 v3(66.9,62.89) 66.9,62.08 66.95,62.03 ; v1(117.86,34.52) v1(117.09,34.52) 116.15,34.52 v1(116.08,34.59)
  vias: v1(57.55,67.1) v1(57.55,59.9) v1(58.35,67.1) v1(58.35,59.9) v1(59.15,67.1) v1(59.15,66.3) v1(59.15,60.7) v1(59.15,59.9) v1(59.95,67.1) v1(59.95,66.3) v1(59.95,60.7) v1(59.95,59.9) v1(60.75,67.1) v1(60.75,66.3) v1(60.75,60.7) v1(60.75,59.9) v1(61.55,67.1) v1(61.55,59.9) v1(113.23,34.62) v1(113.21,33.63) v1(114.12,33.6) v1(114.15,34.59) v1(115.14,34.59) v1(115.11,33.6) v1(116.05,33.6) v1(117.09,33.6) v1(118.06,33.6) v3(70.38,60.46) v3(70.83,60.89) v3(71.09,59.74) v3(71.55,60.17) v3(71.93,59.02) v3(72.26,59.38)
RX_1.8V: length 8
  TOP w0.254: v3(62.41,73.61) v3(62.41,73.03) 62.41,72.8 C75.1 62.41,72.75 v3(62.41,72.42) v3(62.41,71.88)
  BOTTOM w0.102: 58.83,67.64 58.88,67.64 58.99,67.53 59.37,67.53 59.54,67.69 59.63,67.69 59.79,67.53 60.16,67.53 60.33,67.69 ; 60.25,69.04 60.14,69.04 60.11,69.07 59.75,69.07 59.61,68.94
  BOTTOM w0.254: C68.1 60.9,69.65 v1(60.75,69.5) v1(61.55,69.5) ; v1(60.75,57.5) 60.9,57.35 C69.1 61.4,57.35 v1(61.55,57.5)
  BOTTOM w0.305: v1(60.75,67.9) v1(61.55,67.9) ; v1(57.55,67.9) v1(58.35,67.9)
  vias: v1(57.55,68.7) v1(57.55,59.1) v1(57.55,58.3) v1(58.35,68.7) v1(58.35,59.1) v1(58.35,58.3) v1(60.75,68.7) v1(60.75,59.1) v1(60.75,58.3) v1(61.55,68.7) v1(61.55,59.1) v1(61.55,58.3) v1(68.71,63.42) v1(122.28,18.54) v1(122.28,17.48) v1(123.27,18.54) v1(123.27,17.48) v1(124.23,18.54) v1(124.23,17.48) v1(125.22,18.54) v1(125.22,17.48) v3(62.36,54.29) v3(63.07,54.29) v3(64.92,54.69) v3(65.58,54.69) v3(66.12,54.03) v3(66.75,54.03)
RXA_DSA1PD: length 1.6
  BOTTOM w0.127: J7.7 130.63,94.28 Q5.1
RXA_DSA2PD: length 1.6
  BOTTOM w0.127: J7.10 133.17,94.28 Q6.1
RXA_PD2H: length 1.6
  BOTTOM w0.127: J7.31 150.95,94.26 Q13.1
RXA_PD2L: length 1.6
  BOTTOM w0.127: Q14.1 153.49,94.26 J7.34
RXADSA1PD: length 133.1
  L6_SIG w0.127: v1(149.63,44.35) 148.54,45.44 84.46,45.44 82.96,46.94 v1(81.56,46.94)
  L8_PWR_SIG w0.127: J7.8 130.63,98.27 129.46,97.1 129.46,92.79 130,92.25 130,85.37 129.81,85.18 129.81,64.26 132.2,61.86 132.2,61.82 132.91,61.12 132.91,60.19 134.32,58.78 134.95,58.78 140.07,53.66 140.47,53.66 140.86,53.27 140.86,52.39 144.93,48.31 145.24,48.31 148.72,44.83 149.15,44.83 v1(149.63,44.35)
RXADSA2PD: length 138.9
  L6_SIG w0.127: v1(83.41,38.81) 83.84,39.24 150.04,39.24 v1(152.62,41.82)
  L8_PWR_SIG w0.127: J7.11 133.17,98.2 131.8,96.82 131.8,93.37 132.72,92.46 132.72,88.44 131.65,87.38 131.11,87.38 130.44,86.7 130.44,80.91 131.65,79.71 131.65,63.87 133.6,61.92 133.6,61.07 136.34,58.33 137.09,58.33 141.63,53.79 141.63,53.17 142.03,52.77 142.32,52.77 152.62,42.48 v1(152.62,41.82)
RXADSAFAST: length 152.5
  L6_SIG w0.102: 49.15,60.28 53.71,60.28 53.93,60.06 53.93,59.52 v1(54.35,59.1)
  L6_SIG w0.127: 49.15,60.28 43.05,60.28 40.77,58 37.36,58 36.91,58.45 36.54,58.45 36.17,58.07 35.24,58.07 34.4,58.9 34.4,59.82 33.53,60.69 30.85,60.69 30.24,61.29 30.24,62.77 29.97,63.04 29.97,66.76 29.82,66.91 29.82,72.67 31.31,74.16 31.31,83.03 33.85,85.57 33.85,86.52 34.14,86.81 34.4,86.81 40.07,92.48 40.07,93.73 45.65,99.31 46.1,99.31 46.44,99.65 46.44,100.25 47.6,101.4 48.6,101.4 48.86,101.66 48.86,102.07 57.31,110.52 63.54,110.52 63.76,110.3 64.12,110.3 64.52,110.7 72.74,110.7 72.92,110.52 79.67,110.52 79.89,110.74 96.33,110.74 96.83,110.24 100.89,110.24 101.12,110.01 107.29,110.01 108.51,108.79 111.03,108.79 111.32,109.08 116.83,109.08 J9.2
RXAPD2H: length 135.1
  L6_SIG w0.127: v1(155.91,44.53) 155.32,45.11 153.57,45.11 149.3,40.84 84.68,40.84 v1(83.41,42.11)
  L8_PWR_SIG w0.127: v1(155.91,44.53) 155.32,45.11 155.32,49.23 154.47,50.08 154.47,68.59 154.34,68.71 154.34,70.29 154.72,70.67 154.72,84.44 155.35,85.06 155.35,92.02 154.56,92.81 154.56,94.55 154.77,94.76 154.77,95.13 154.56,95.35 154.56,98.7 153.9,99.36 151.99,99.36 J7.32
RXAPD2L: length 126.6
  L6_SIG w0.127: v1(80.54,48.26) 83.64,48.26 85.9,46 149.86,46 150.98,47.12 v1(152.86,47.12)
  L8_PWR_SIG w0.127: v1(152.86,47.12) 153,47.26 153,54.55 152.15,55.4 152.15,55.96 152.16,55.98 152.16,56.34 152.15,56.36 152.15,60.56 152.39,60.8 152.39,61.17 152.15,61.41 152.15,63.79 152.21,63.85 152.21,64.22 152.15,64.28 152.15,70 152.82,70.67 152.82,73.69 152.86,73.73 152.86,85.15 152.84,85.16 152.84,85.53 152.86,85.54 152.86,92.86 152.35,93.37 152.35,97.03 153.49,98.17 J7.35
RXB_DSA1PD: length 1.6
  BOTTOM w0.127: J7.13 135.71,94.26 Q7.1
RXB_DSA2PD: length 1.6
  BOTTOM w0.127: Q8.1 138.25,94.28 J7.16
RXB_PD2H: length 1.6
  BOTTOM w0.127: Q15.1 156.03,94.26 J7.37
RXB_PD2L: length 1.6
  BOTTOM w0.127: Q16.1 158.57,94.26 J7.40
RXBDSA1PD: length 139.5
  L6_SIG w0.127: v1(83.41,37.13) 83.44,37.13 84.47,38.16 131.12,38.16 131.4,38.44 131.79,38.44 132.07,38.16 152.79,38.16 v1(153.24,38.61)
  L8_PWR_SIG w0.127: v1(153.24,38.61) 153.71,39.08 153.71,43.47 148.45,48.73 148.2,48.73 144.56,52.36 144.56,53.4 144.3,53.66 144.11,53.66 142.05,55.71 142.01,55.71 141.74,55.98 141.74,56.02 138.75,59.02 138.75,59.42 138.49,59.68 138.16,59.68 135.85,61.98 135.85,71.32 135.43,71.74 135.43,79.38 135.65,79.59 135.65,92.57 134.76,93.46 134.76,97.37 J7.14
RXBDSA2PD: length 133.7
  L6_SIG w0.127: v1(83.44,40.49) 83.54,40.39 149.89,40.39 v1(153.99,44.49)
  L8_PWR_SIG w0.127: v1(153.99,44.49) 153.99,44.72 148.42,50.28 148.42,50.3 148.16,50.56 148.15,50.56 146.47,52.23 146.47,53.4 146.21,53.66 145.96,53.66 140.65,58.97 140.65,59.42 138.77,61.3 138.77,78.4 137.97,79.2 137.97,79.91 138.13,80.06 138.13,92.61 137.3,93.44 137.3,97.37 J7.17
RXBDSAFAST: length 154.8
  L6_SIG w0.102: 59.9,55.36 58.98,56.29 58.98,56.33 58.77,56.54 58.77,59.34 58.6,59.51 57.14,59.51 v1(56.75,59.9)
  L6_SIG w0.127: 59.9,55.36 60.09,55.18 60.09,54.5 60.35,54.24 61.02,54.24 63.98,51.28 138.61,51.28 139.32,51.99 v1(139.32,52.45)
  L8_PWR_SIG w0.127: v1(139.32,52.45) 138.82,52.95 138.82,53.58 138.53,53.87 138.11,53.87 134.43,57.55 134.43,58.1 131.15,61.38 130.67,61.38 127.89,64.16 127.89,74.19 128.5,74.8 128.5,76.78 127.94,77.34 127.94,92.68 126.7,93.93 126.7,102.87 125.73,103.84 123.04,103.84 121.72,105.16 121.72,106.81 120.68,107.85 J9.5
RXBPD2H: length 132.9
  L6_SIG w0.127: v1(157.66,44.55) 156.67,45.54 153.11,45.54 150.5,42.93 84.43,42.93 v1(83.44,43.92)
  L8_PWR_SIG w0.127: v1(157.66,44.55) 157.05,45.16 157.05,49.43 156.24,50.24 156.24,65.66 154.93,66.97 154.93,69.42 156.38,70.87 156.38,85.46 155.97,85.86 155.97,86.65 156.38,87.06 156.38,87.74 155.97,88.14 155.97,92.47 155.08,93.36 155.08,97.4 156.01,98.32 J7.38
RXBPD2L: length 134.3
  L6_SIG w0.127: v1(83.44,45.44) 83.44,45.42 85.42,43.43 150.11,43.43 152.78,46.1 157.81,46.1 v1(159.33,44.58)
  L8_PWR_SIG w0.127: J7.41 159.52,97.37 159.52,95.39 159.47,95.34 159.47,90.38 159.52,90.33 159.52,86.37 159.47,86.32 159.47,85.95 159.52,85.9 159.52,75.83 159.91,75.45 159.91,72.5 159.69,72.29 159.69,66.12 160.3,65.51 160.3,53.55 160.99,52.86 160.99,52.14 160.77,51.92 160.77,45.86 159.49,44.58 v1(159.33,44.58)
RXC_DSA1PD: length 1.6
  BOTTOM w0.127: J7.19 140.79,94.28 Q9.1
RXC_DSA2PD: length 1.6
  BOTTOM w0.127: J7.22 143.33,94.28 Q10.1
RXC_PD2H: length 1.6
  BOTTOM w0.127: J7.43 161.11,94.28 Q17.1
RXC_PD2L: length 1.6
  BOTTOM w0.127: J7.46 163.65,94.28 Q18.1
RXCDSA1PD: length 87.7
  L4_SIG w0.127: v1(140.77,77.44) 139.78,76.46 100.59,76.46 98.86,74.73 86.03,74.73 83.03,77.72 v1(77.65,77.72)
  L8_PWR_SIG w0.127: v1(140.77,77.44) 140.77,77.5 139.83,78.44 139.83,80.06 140.09,80.33 140.09,93.15 139.42,93.83 139.42,96.95 J7.20
RXCDSA2PD: length 80.8
  TOP w0.127: v1(120.8,86.46) 120.76,86.5 120.76,90.51 122.97,92.72 v1(122.97,98.67)
  L4_SIG w0.127: J7.23 141.86,99.8 124.16,99.8 123.02,98.67 v1(122.97,98.67) ; v1(120.8,86.46) 119.99,85.65 106.12,85.65 105.92,85.45 100.48,85.45 100.03,85.9 91.51,85.9 91.32,85.71 87.64,85.71 81.94,80.01 v1(77.65,80.01)
RXCDSAFAST: length 116.3
  L4_SIG w0.102: 49.93,71.5 49.93,67.78 50.19,67.52 53.96,67.52 54.34,67.9 v1(54.35,67.9)
  L4_SIG w0.127: 49.93,71.5 49.93,71.88 50.83,72.78 50.83,74.16 50.29,74.7 50.29,75.56 50.59,75.87 50.59,76.79 50.44,76.94 50.44,82.4 50.83,82.79 50.83,95.26 53.7,98.12 53.7,99.35 54.68,100.33 55.35,100.33 v1(57.43,102.41)
  L6_SIG w0.127: J9.8 122.19,108.8 119.9,108.8 119.23,108.13 119.23,107.57 118.52,106.86 117.53,106.86 116.85,107.53 114.31,107.53 113.59,106.81 112.63,106.81 111.14,108.31 107.98,108.31 107.23,109.05 101.31,109.05 100.66,109.7 96.57,109.7 95.96,110.31 80.77,110.31 80.4,109.94 72.32,109.94 71.93,110.33 67.41,110.33 66.55,109.47 65.83,109.47 65.78,109.53 64.54,109.53 58.24,103.23 v1(57.43,102.41)
RXCPD2H: length 107.5
  TOP w0.127: J7.44 160.15,97.36 160.15,86.36 v1(159.92,86.13)
  L4_SIG w0.127: v1(77.65,79.22) 80.15,79.22 80.25,79.12 84.56,79.12 89.72,84.28 92.18,84.28 92.47,83.98 97.22,83.98 97.34,84.1 100.08,84.1 100.62,84.65 101.56,84.65 101.57,84.63 106.53,84.63 107.01,85.12 120.09,85.12 122.71,87.73 122.71,91.49 123.51,92.29 157.32,92.29 159.23,90.37 159.23,86.82 v1(159.92,86.13)
RXCPD2L: length 100.5
  L4_SIG w0.127: v1(77.65,82.58) 77.65,82.55 77.19,82.09 77.19,81.53 77.36,81.37 79.64,81.37 82.09,83.82 82.09,84.04 86.59,88.54 88.65,88.54 91.64,91.54 93.7,91.54 94.95,92.79 97.26,92.79 97.9,93.43 110,93.43 110.86,94.3 111.85,94.3 112.55,95 124.99,95 125.16,94.83 125.95,94.83 126.5,95.39 126.5,95.67 127.58,96.75 148.18,96.75 149.4,97.97 149.4,100.71 150.57,101.88 151.28,101.88 151.75,101.41 152.51,101.41 153.09,101.98 154.05,101.98 154.79,101.24 154.79,100.76 156.26,99.29 158.95,99.29 158.97,99.28 161.73,99.28 162.69,98.32 J7.47
RXD_DSA1PD: length 1.6
  BOTTOM w0.127: J7.25 145.87,94.26 Q11.1
RXD_DSA2PD: length 1.6
  BOTTOM w0.127: J7.28 148.41,94.26 Q12.1
RXD_PD2H: length 1.6
  BOTTOM w0.127: Q19.1 166.19,94.26 J7.49
RXD_PD2L: length 1.6
  BOTTOM w0.127: Q20.1 168.73,94.26 J7.52
RXDDSA1PD: length 78.5
  L4_SIG w0.127: v1(77.67,83.36) 77.67,83.52 84.23,90.07 88.59,90.07 91.67,93.14 91.67,94.41 93.15,95.9 94.37,95.9 96.31,97.84 101.17,97.84 102.11,96.9 107.59,96.9 108.12,97.43 119.98,97.43 120.52,96.9 122.86,96.9 123.29,97.33 125.91,97.33 126.5,97.93 126.5,98.21 127.71,99.42 141.25,99.42 142.38,98.29 142.38,97.93 142.95,97.36 144.91,97.36 J7.26
RXDDSA2PD: length 80.5
  L4_SIG w0.127: v1(77.65,81.81) 85.18,89.34 88.61,89.34 92.27,93 92.27,93.66 93.62,95.01 94.27,95.01 95.52,96.25 97.65,96.25 97.9,96.51 97.9,96.81 98.16,97.07 99.16,97.07 100.04,96.18 105.26,96.18 105.45,96.36 105.73,96.36 105.84,96.25 105.85,96.25 106.86,95.25 110.24,95.25 110.87,95.88 112.9,95.88 113.33,95.45 122.05,95.45 123.47,96.88 126.14,96.88 126.57,97.31 128.68,97.31 128.85,97.14 129.22,97.14 129.38,97.31 142.11,97.31 142.37,97.05 147.14,97.05 J7.29
RXDDSAFAST: length 102
  TOP w0.127: v1(121.59,87.93) 121.75,87.77 124.35,87.77 124.97,88.39 124.97,92.15 124.43,92.68 124.43,106.6 J9.11
  L4_SIG w0.102: 58.77,71.5 58.77,68.58 58.51,68.32 58.23,68.32 57.97,68.06 57.97,67.78 57.71,67.52 57.17,67.52 v1(56.75,67.1)
  L4_SIG w0.127: 58.77,71.5 58.77,71.82 59.01,72.06 59.01,73.01 60.67,74.67 60.67,75.09 64.24,78.66 65.1,78.66 68.05,81.62 73.27,81.62 74.17,80.71 76.09,80.71 76.44,81.06 77.55,81.06 77.74,80.87 80.83,80.87 86.7,86.75 88.28,86.75 88.54,87.01 90.91,87.01 91.56,86.36 99.16,86.36 100,87.2 105.71,87.2 106.04,87.53 109.73,87.53 110.12,87.13 110.93,87.13 111.62,87.82 121.48,87.82 v1(121.59,87.93)
RXDPD2H: length 115.3
  L4_SIG w0.127: v1(165.3,75.08) 165.3,74.6 164.41,73.71 162.77,73.71 162.39,74.09 162.39,74.51 161.02,75.88 106.57,75.88 104.93,74.24 85.27,74.24 82.92,76.59 79.4,76.59 79.02,76.96 v1(77.65,76.96)
  L8_PWR_SIG w0.127: v1(165.3,75.08) 165.3,80.52 165.49,80.71 165.49,94.6 165.24,94.86 165.24,97.37 J7.50
RXDPD2L: length 118
  L4_SIG w0.127: v1(77.65,76.2) 77.84,76.01 82.13,76.01 84.46,73.69 100.05,73.69 100.98,72.76 155.11,72.76 157.06,74.71 161.6,74.71 161.86,74.45 161.86,73.75 162.89,72.72 164.77,72.72 v1(167.11,75.06)
  L8_PWR_SIG w0.127: J7.53 167.67,97.26 167.67,92.91 167.84,92.74 167.84,80.85 167.35,80.35 167.35,75.32 167.11,75.08 v1(167.11,75.06)
RXDSASW: length 153.4
  L4_SIG w0.102: v1(55.15,58.3) 55.38,58.3 55.76,58.68 56.12,58.68 56.34,58.9 56.34,67.25 56.11,67.48 55.03,67.48 54.73,67.78 54.73,69.66 54.51,69.88 54.2,69.88 53.93,70.15 53.93,71.26 53.92,71.26 53.92,71.5
  L4_SIG w0.127: 53.92,71.5 53.92,72.36 54.24,72.68 54.24,75.03 55.4,76.19 55.4,80.12 59.44,84.16 59.44,93.48 57.67,95.26 v1(57.67,98.32)
  L6_SIG w0.127: v1(57.67,98.32) 57.9,98.32 58.99,99.4 59.4,99.4 59.57,99.23 60.22,99.23 62.15,101.16 62.15,101.82 63.63,103.3 64.22,103.3 64.92,104.01 64.92,104.26 66.95,106.29 68.92,106.29 69.36,105.85 72.01,105.85 72.32,106.15 89.61,106.15 91.11,107.65 93.09,107.65 93.98,106.76 95.58,106.76 96.29,106.05 102.03,106.05 102.46,106.48 106.44,106.48 106.78,106.13 110.45,106.13 113.23,103.35 126.44,103.35 127.25,104.17 146.41,104.17 147.02,104.77 147.02,105.23 148.44,106.65 150.01,106.65 150.22,106.86 155.17,106.86 J9.47
RXFBNCO0: length 134.2
  L4_SIG w0.102: 49.15,60.32 49.95,59.52 55.27,59.52 55.53,59.26 55.53,58.94 55.31,58.72 55.03,58.72 54.77,58.46 54.77,58.14 55.03,57.88 55.53,57.88 55.91,57.5 v1(55.95,57.5)
  L4_SIG w0.127: 49.15,60.32 48.92,60.56 48.92,67.56 48.62,67.86 48.62,72.73 49.2,73.3 49.2,76.3 48.7,76.79 48.7,77.53 49.09,77.92 49.09,80.16 49.38,80.45 49.38,85.85 49.04,86.2 49.04,87.63 48.7,87.96 48.7,94.55 52.5,98.35 52.5,99.97 60.46,107.93 66.25,107.93 66.49,107.69 67.59,107.69 68.07,108.17 70.99,108.17 71.18,108.37 71.55,108.37 71.74,108.17 92.3,108.17 93.58,106.9 95.6,106.9 96.13,107.43 98.95,107.43 100.24,106.13 100.62,106.13 101.16,106.68 114.27,106.68 114.4,106.55 114.4,106.53 114.66,106.27 115.03,106.27 115.29,106.53 115.29,106.55 115.42,106.68 127.08,106.68 128.22,107.82 J9.14
RXFBNCO1: length 143.6
  L4_SIG w0.102: 65.15,61.11 58.72,61.11 58.35,60.74 v1(58.35,60.7)
  L4_SIG w0.127: 65.15,61.11 66.69,61.11 67.12,60.69 68.52,60.69 72.44,56.77 140.54,56.77 141.35,55.96 v1(141.35,55.6)
  L8_PWR_SIG w0.127: J9.17 131.9,106.71 131.9,103.63 132.78,102.76 132.78,102.71 133.04,102.45 133.08,102.45 134.24,101.3 134.24,93.22 135.01,92.44 135.01,83.1 134.28,82.36 134.28,78.29 134.91,77.65 134.91,71.67 135.25,71.32 135.25,61.09 138.24,58.1 138.24,57.7 138.66,57.28 139.77,57.28 141.35,55.7 v1(141.35,55.6)
RXFBNCO2: length 100.8
  L4_SIG w0.102: 55.55,71.5 55.55,69.95 55.95,69.55 v1(55.95,69.5)
  L4_SIG w0.127: 55.55,71.5 55.55,72.67 55.8,72.92 55.8,73.94 57.06,75.19 57.06,76.85 64.28,84.07 66.95,84.07 67.08,84.2 67.08,84.23 67.49,84.63 76.25,84.63 78.99,87.38 79.4,87.38 82.68,90.66 82.95,90.66 84.49,92.2 87.81,92.2 88.32,92.71 88.97,92.71 90.06,93.8 90.06,94.35 91.31,95.61 91.64,95.61 92.3,96.27 92.3,96.7 94.54,98.93 98.93,98.93 99.44,98.42 105.03,98.42 105.83,99.23 107.1,99.23 108.41,97.92 114.68,97.92 116.33,99.57 122.89,99.57 126.59,103.28 131.22,103.28 132.33,104.39 132.33,106.88 J9.20
RXFBNCO3: length 118.8
  TOP w0.127: v1(132.84,85.67) 132.84,86.77 133.73,87.66 134.32,87.66 135.01,88.35 135.01,91.85 136.66,93.5 136.66,103.64 136.8,103.78 136.8,106.88 J9.23
  L4_SIG w0.102: 65.15,69.14 64.93,69.14 64.91,69.12 62.99,69.12 62.98,69.13 62.77,68.92 62.77,67.78 62.47,67.48 62.19,67.48 61.97,67.26 61.97,66.98 61.71,66.72 58.77,66.72 v1(58.35,66.3)
  L4_SIG w0.127: 65.15,69.14 72.92,69.14 75.73,71.95 76.67,71.95 77.88,70.74 124.99,70.74 125.34,70.4 126.28,70.4 126.62,70.74 v1(133.48,70.74)
  L8_PWR_SIG w0.127: v1(132.84,85.67) 132.84,80.39 133.48,79.76 v1(133.48,70.74)
RXFBSW1: length 176
  L6_SIG w0.102: v1(56.75,59.1) 57.17,58.68 57.39,58.68 57.39,58.68 57.71,58.68 57.93,58.46 57.93,56.54 58.19,56.28 58.51,56.28 58.73,56.06 58.73,55.54 58.91,55.36
  L6_SIG w0.127: v1(160.43,52.55) 158.78,50.9 65.82,50.9 65.79,50.93 65.42,50.93 65.18,50.68 63.74,50.68 63.32,51.1 62.75,51.1 62.17,51.67 62.17,52.23 60.64,53.77 60.23,53.77 59.24,54.75 59.24,55.03 58.91,55.36
  L8_PWR_SIG w0.127: J9.38 149.42,108.72 149.42,108.82 149.68,109.08 149.77,109.08 149.81,109.12 153.97,109.12 154.56,108.53 154.56,108.26 154.57,108.24 154.57,104.91 154.56,104.9 154.56,100.86 156.15,99.28 156.43,99.28 157.03,98.67 157.03,93.18 158.32,91.9 158.32,90.24 158.31,90.23 158.31,89.86 158.31,89.85 158.31,83.51 158.05,83.25 158.05,76.87 158.32,76.61 158.32,70.45 157.72,69.86 157.72,67.32 157.94,67.1 157.94,64.57 158.45,64.06 158.45,54.76 159.8,53.4 159.8,53.17 v1(160.43,52.55)
RXFBSW2: length 145.3
  L4_SIG w0.102: v1(56.75,67.9) 57.17,68.32 57.71,68.32 57.97,68.58 57.97,71.5
  L4_SIG w0.127: 57.97,71.5 57.97,71.76 58.45,72.24 58.45,73.1 58.28,73.27 58.28,73.64 59.4,74.76 59.83,74.76 60.09,75.02 60.09,75.17 66.24,81.32 66.79,81.32 67.5,82.02 73.81,82.02 v1(74.55,81.28) ; v1(89.76,80.8) 90.5,80.06 97.61,80.06 98.55,81 102.62,81 103.2,81.58 126.62,81.58 127.71,80.49 144.09,80.49 146.95,77.64 146.95,77.29 147.22,77.01 v1(150.34,77.01)
  L8_PWR_SIG w0.127: v1(89.76,80.8) 89.28,81.28 v1(74.55,81.28) ; J9.41 151.08,107.55 152.15,106.48 152.15,104.27 150,102.12 150,92.95 150.34,92.61 v1(150.34,77.01) 150.34,71.35 149.73,70.74 v1(149.25,70.74)
